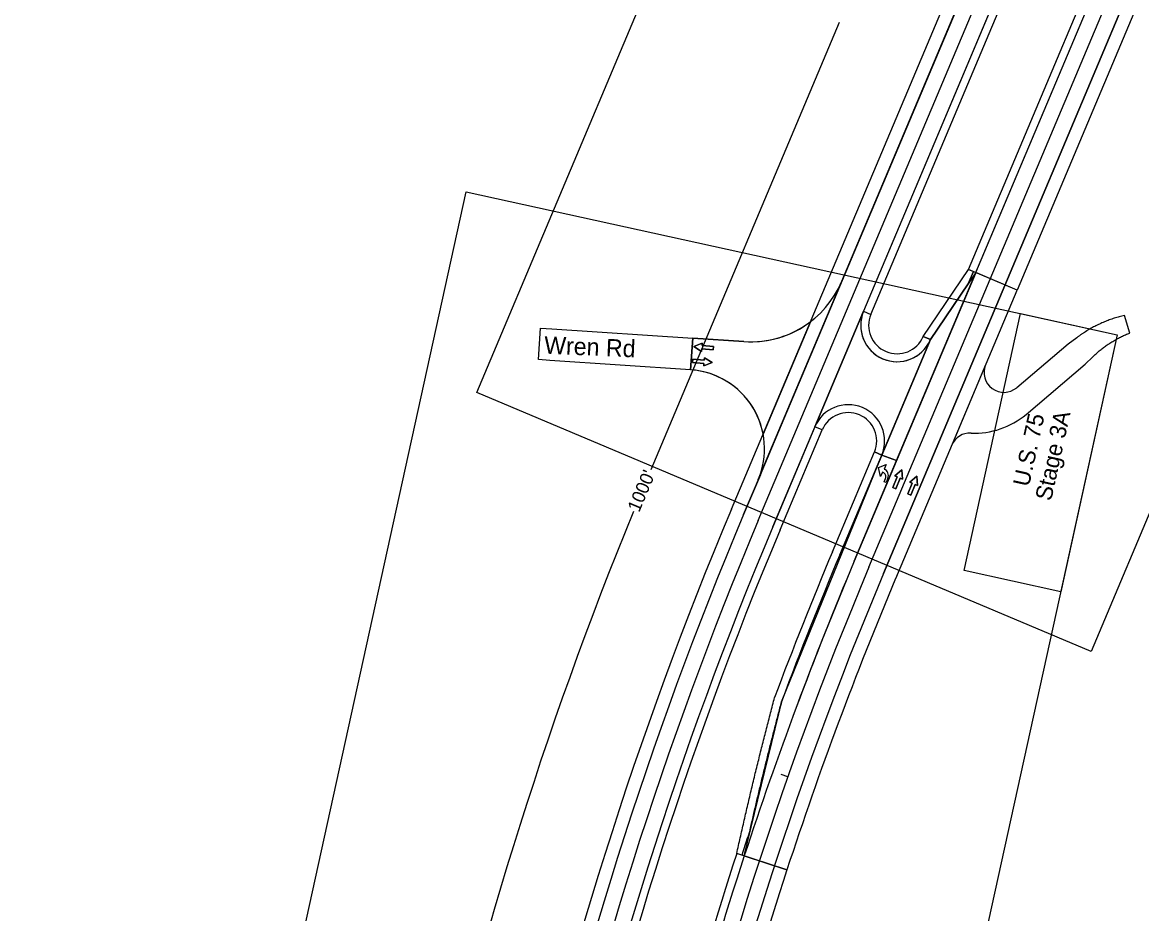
# Model space of a CAD drawing. Extents: x 14104283 to 14120882, y 8635219 to 8671666.
# Drawn here: x 14108596 to 14109444, y 8645129 to 8645804 of the extents above; entities that cross this region are included whole.
import ezdxf

# ---------------------------------------------------------------- set-up
doc = ezdxf.new("R2010")
doc.units = 0
for name, color, linetype in [('Cell', 7, 'Continuous'), ('dsnNonPlotable', 7, 'Continuous'), ('dsnPaintExistingEdgeLineRightWhite', 7, 'Continuous'), ('dsnPaintExistingLaneLineWhite', 7, 'Continuous'), ('dsnPaintPlaceBrokenLineWhite', 7, 'Continuous'), ('dsnPaintPlaceEdgeLineLeftYellow', 7, 'Continuous'), ('dsnPaintPlaceEdgeLineRightWhite', 7, 'Continuous'), ('dsnPaintRemoveDoubleCenterLineYellow', 7, 'Continuous'), ('dsnShadingGranular', 7, 'Continuous'), ('dsnShadingPaved', 7, 'Continuous'), ('dsnStdLabel', 7, 'Continuous'), ('dsnStgShadingPrevPav', 7, 'Continuous'), ('dsnTextFinalPlan', 7, 'Continuous'), ('dsnTextOverlapEven', 7, 'Continuous'), ('TextAlignmentLrg', 7, 'Continuous')]:
    doc.layers.add(name, color=color, linetype=linetype)

msp = doc.modelspace()

# ---------------------------------------------------------------- linework, layer by layer
at = {"layer": 'Cell'}
for p, q in [((14109248.25, 8645463.34), (14109247.95, 8645463.46)), ((14109249.06, 8645465.84), (14109249.23, 8645465.77))]:
    msp.add_line(p, q, dxfattribs=at)
for points in [[(14109119.8, 8645558.61), (14109119.6, 8645556.12), (14109110.88, 8645556.82), (14109110.73, 8645554.95), (14109104.75, 8645558.56), (14109111.23, 8645561.18), (14109111.08, 8645559.31)], [(14109103.82, 8645546.48), (14109104.02, 8645548.97), (14109112.74, 8645548.27), (14109112.89, 8645550.14), (14109118.87, 8645546.53), (14109112.39, 8645543.91), (14109112.54, 8645545.78)], [(14109257.91, 8645450.9), (14109255.59, 8645451.85), (14109258.91, 8645459.95), (14109257.18, 8645460.66), (14109262.44, 8645465.25), (14109262.96, 8645458.29), (14109261.23, 8645459)], [(14109269.36, 8645446.08), (14109267.05, 8645447.03), (14109270.37, 8645455.12), (14109268.63, 8645455.83), (14109273.9, 8645460.43), (14109274.42, 8645453.46), (14109272.68, 8645454.17)]]:
    msp.add_lwpolyline(points, close=True, dxfattribs=at)
for points in [[(14109111.08, 8645559.31), (14109111.23, 8645561.18), (14109104.75, 8645558.56), (14109110.73, 8645554.95), (14109110.88, 8645556.82), (14109119.6, 8645556.12), (14109119.8, 8645558.61), (14109111.08, 8645559.31)], [(14109112.54, 8645545.78), (14109112.39, 8645543.91), (14109118.87, 8645546.53), (14109112.89, 8645550.14), (14109112.74, 8645548.27), (14109104.02, 8645548.97), (14109103.82, 8645546.48), (14109112.54, 8645545.78)], [(14109244.88, 8645466.97), (14109250.61, 8645469.19), (14109249.06, 8645465.84)], [(14109244.88, 8645466.97), (14109250.61, 8645469.19), (14109249.06, 8645465.84)], [(14109247.95, 8645463.46), (14109246.4, 8645460.11), (14109244.88, 8645466.97)], [(14109247.95, 8645463.46), (14109246.4, 8645460.11), (14109244.88, 8645466.97)], [(14109248.25, 8645463.34), (14109247.95, 8645463.46)], [(14109249.06, 8645465.84), (14109249.23, 8645465.77)], [(14109261.23, 8645459), (14109262.96, 8645458.29), (14109262.44, 8645465.25), (14109257.18, 8645460.66), (14109258.91, 8645459.95), (14109255.59, 8645451.85), (14109257.91, 8645450.9), (14109261.23, 8645459)], [(14109272.68, 8645454.17), (14109274.42, 8645453.46), (14109273.9, 8645460.43), (14109268.63, 8645455.83), (14109270.37, 8645455.12), (14109267.05, 8645447.03), (14109269.36, 8645446.08), (14109272.68, 8645454.17)], [(14109251.88, 8645459.03), (14109250.5, 8645455.62), (14109249.11, 8645456.18), (14109250.1, 8645458.62)], [(14109251.88, 8645459.03), (14109250.5, 8645455.62), (14109249.11, 8645456.18), (14109250.1, 8645458.62)]]:
    msp.add_lwpolyline(points, dxfattribs=at)
for centre, major_axis in [((14109246.86, 8645459.93), (-1.38, -3.41)), ((14109246.86, 8645459.93), (-1.38, -3.41)), ((14109247.26, 8645460.9), (-1.97, -4.87)), ((14109247.26, 8645460.9), (-1.97, -4.87))]:
    msp.add_ellipse(centre, major_axis=major_axis, ratio=0.9474, start_param=1.570796, end_param=3.141593, dxfattribs=at)
at = {"layer": 'dsnNonPlotable'}
for points in [[(14108940.51, 8645523.76), (14109549.08, 8646968.3), (14110014.46, 8646772.24), (14109405.89, 8645327.7)], [(14108596.11, 8644144.86), (14108932.49, 8645675.84), (14109425.73, 8645567.47), (14109089.34, 8644036.49)]]:
    msp.add_lwpolyline(points, close=True, dxfattribs=at)
at = {"layer": 'dsnPaintExistingEdgeLineRightWhite'}
msp.add_line((14109248.59, 8645386.79), (14110924.38, 8649364.51), dxfattribs=at)
msp.add_arc((14111877.79, 8644279.13), 2853, 157.1547, 167.84877, dxfattribs=at)
at = {"layer": 'dsnPaintExistingLaneLineWhite'}
msp.add_line((14109226.48, 8645396.11), (14109258.54, 8645472.23), dxfattribs=at)
msp.add_arc((14111877.79, 8644279.13), 2877, 157.1547, 159.50271, dxfattribs=at)
at = {"layer": 'dsnPaintPlaceBrokenLineWhite'}
for p, q in [((14109153.67, 8645426.78), (14110829.45, 8649404.5)), ((14109237.53, 8645391.45), (14110075.43, 8647380.31))]:
    msp.add_line(p, q, dxfattribs=at)
for centre, radius in [((14111877.8, 8644279.13), 2956), ((14111877.79, 8644279.13), 2865)]:
    msp.add_arc(centre, radius, 157.1547, 167.84877, dxfattribs=at)
at = {"layer": 'dsnPaintPlaceEdgeLineLeftYellow'}
for p, q in [((14109318.52, 8645614.6), (14110902.26, 8649373.83)), ((14109283.61, 8645562.93), (14109318.29, 8645614.05)), ((14109196.6, 8645497.77), (14109164.73, 8645422.12)), ((14109171.7, 8645290.75), (14109247.29, 8645476.42)), ((14109143.12, 8645172.82), (14109171.7, 8645290.75))]:
    msp.add_line(p, q, dxfattribs=at)
msp.add_lwpolyline([(14111383.58, 8650689.44), (14110840.51, 8649399.84), (14109233.49, 8645585.32)], dxfattribs=at)
for centre, radius, start, end in [((14109258.83, 8645574.64), 27.5, 157.1547, 335.84151), ((14109221.94, 8645487.09), 27.5, 67.1547, 157.1547), ((14109221.94, 8645487.09), 27.5, 337.1547, 67.1547), ((14111877.8, 8644279.13), 2944, 157.1547, 167.84877), ((14111877.79, 8644279.13), 2877, 161.90302, 167.84877)]:
    msp.add_arc(centre, radius, start, end, dxfattribs=at)
at = {"layer": 'dsnPaintPlaceEdgeLineRightWhite'}
msp.add_line((14109155.29, 8645461.54), (14109142.61, 8645431.44), dxfattribs=at)
msp.add_lwpolyline([(14111344.56, 8650658.61), (14110818.39, 8649409.15), (14109217.02, 8645608.05)], dxfattribs=at)
msp.add_arc((14111877.8, 8644279.13), 2968, 157.1547, 167.84877, dxfattribs=at)
at = {"layer": 'dsnPaintRemoveDoubleCenterLineYellow'}
msp.add_line((14109237.53, 8645391.45), (14110075.43, 8647380.31), dxfattribs=at)
msp.add_arc((14111877.79, 8644279.13), 2865, 157.1547, 167.84877, dxfattribs=at)
at = {"layer": 'dsnShadingGranular'}
msp.add_line((14109325.98, 8645544.73), (14109300.38, 8645483.96), dxfattribs=at)
at = {"layer": 'dsnShadingPaved'}
for p, q in [((14109258.54, 8645472.23), (14110902.26, 8649373.83)), ((14110924.38, 8649364.51), (14109248.59, 8645386.79)), ((14109318.29, 8645614.05), (14109258.54, 8645472.23)), ((14109283.61, 8645562.93), (14109318.29, 8645614.05)), ((14109153.74, 8645457.84), (14109217.02, 8645608.05)), ((14109196.6, 8645497.77), (14109233.49, 8645585.32)), ((14109104.08, 8645564.95), (14109102.47, 8645541)), ((14109142.87, 8645562.34), (14109104.08, 8645564.95)), ((14109171.7, 8645290.75), (14109247.29, 8645476.42)), ((14109247.29, 8645476.42), (14109258.54, 8645472.23)), ((14109258.54, 8645472.23), (14109247.29, 8645476.42)), ((14109143.12, 8645172.82), (14109171.7, 8645290.75))]:
    msp.add_line(p, q, dxfattribs=at)
for points in [[(14118413.25, 8667444.25), (14110818.39, 8649409.15), (14109142.61, 8645431.44)], [(14109164.73, 8645422.12), (14110840.51, 8649399.84), (14118435.37, 8667434.94)]]:
    msp.add_lwpolyline(points, dxfattribs=at)
for centre, radius, start, end in [((14109147.9, 8645637.17), 75, 266.1547, 337.1547), ((14109258.83, 8645574.64), 27.5, 157.1547, 247.1547), ((14109258.83, 8645574.64), 27.5, 247.1547, 335.84151), ((14109098.44, 8645481.13), 60, 337.1547, 86.1547), ((14109221.94, 8645487.09), 27.5, 67.1547, 157.1547), ((14109221.94, 8645487.09), 27.5, 337.1547, 67.1547), ((14111877.8, 8644279.13), 2968, 157.1547, 167.84877), ((14111877.8, 8644279.13), 2944, 157.1547, 167.84877), ((14111877.79, 8644279.13), 2853, 157.1547, 167.84877), ((14111877.79, 8644279.13), 2877, 161.90302, 167.84877)]:
    msp.add_arc(centre, radius, start, end, dxfattribs=at)
at = {"layer": 'dsnStdLabel'}
msp.add_line((14109214.96, 8645804.07), (14109072.17, 8645465.12), dxfattribs=at)
msp.add_arc((14111877.8, 8644279.13), 3046, 157.72718, 167.84877, dxfattribs=at)
at = {"layer": 'dsnStgShadingPrevPav'}
for p, q in [((14109133.4, 8645435.32), (14110809.18, 8649413.03)), ((14110818.39, 8649409.15), (14109142.61, 8645431.44)), ((14109318.52, 8645614.6), (14109226.48, 8645396.11)), ((14109318.52, 8645614.6), (14109226.48, 8645396.11)), ((14109312.8, 8645606.16), (14109316.68, 8645615.38)), ((14109316.68, 8645615.38), (14109318.52, 8645614.6)), ((14109349.86, 8645601.4), (14109318.52, 8645614.6)), ((14109155.29, 8645461.54), (14109217.02, 8645608.05)), ((14109284.17, 8645563.96), (14109312.8, 8645606.16)), ((14109257.81, 8645382.91), (14109349.86, 8645601.4)), ((14109196.6, 8645497.77), (14109233.49, 8645585.32)), ((14109233.49, 8645585.32), (14109196.6, 8645497.77)), ((14109233.49, 8645585.32), (14109239.01, 8645582.99)), ((14109435.19, 8645568.84), (14109431.12, 8645582.24)), ((14109193.28, 8645577.45), (14109157.4, 8645492.29)), ((14109102.47, 8645541), (14109104.08, 8645564.95)), ((14109104.08, 8645564.95), (14109142.87, 8645562.34)), ((14109215.42, 8645400.77), (14109284.17, 8645563.96)), ((14109284.17, 8645563.96), (14109247.29, 8645476.42)), ((14109278.64, 8645566.29), (14109284.17, 8645563.96)), ((14109325.98, 8645544.73), (14109300.38, 8645483.96)), ((14109356.61, 8645507.27), (14109401.37, 8645545.2)), ((14109401.37, 8645545.2), (14109407.22, 8645550.87)), ((14109196.6, 8645497.77), (14109164.73, 8645422.12)), ((14109196.6, 8645497.77), (14109164.73, 8645422.12)), ((14109170.26, 8645419.79), (14109202.13, 8645495.44)), ((14109202.13, 8645495.44), (14109196.6, 8645497.77)), ((14109202.13, 8645495.44), (14109196.6, 8645497.77)), ((14109209.89, 8645403.09), (14109241.76, 8645478.75)), ((14109247.29, 8645476.42), (14109215.42, 8645400.77)), ((14109247.29, 8645476.42), (14109241.76, 8645478.75)), ((14109241.76, 8645478.75), (14109247.29, 8645476.42)), ((14109142.61, 8645431.44), (14109155.29, 8645461.54)), ((14109175.44, 8645162.26), (14109137.42, 8645174.69)), ((14109141.22, 8645173.44), (14109137.42, 8645174.69)), ((14109143.12, 8645172.82), (14109141.22, 8645173.44)), ((14109143.12, 8645172.82), (14109175.44, 8645162.26))]:
    msp.add_line(p, q, dxfattribs=at)
for points in [[(14109239.01, 8645582.99), (14111389.11, 8650687.11), (14111383.58, 8650689.44), (14109233.49, 8645585.32)], [(14109313, 8645616.93), (14110622.7, 8648725.72), (14110659.7, 8648710.5), (14109349.86, 8645601.4)], [(14109278.64, 8645566.29), (14109313, 8645616.93), (14109316.68, 8645615.38), (14109312.8, 8645606.16), (14109284.17, 8645563.96)], [(14108987.25, 8645548.72), (14108988.7, 8645572.67), (14108997.4, 8645572.12), (14109104.08, 8645564.95), (14109102.47, 8645541), (14108995.79, 8645548.17)]]:
    msp.add_lwpolyline(points, close=True, dxfattribs=at)
for points in [[(14111383.58, 8650689.44), (14110840.51, 8649399.84), (14109233.49, 8645585.32)], [(14109217.02, 8645608.05), (14110818.39, 8649409.15), (14111344.56, 8650658.61)], [(14109395, 8645565.3), (14109388.44, 8645560.45), (14109349.5, 8645527.46)]]:
    msp.add_lwpolyline(points, dxfattribs=at)
for centre, radius, start, end in [((14109258.83, 8645574.64), 21.5, 157.1547, 247.1547), ((14109147.9, 8645637.17), 75, 266.1547, 307.22827), ((14109258.83, 8645574.64), 21.5, 247.1547, 337.1547), ((14109339.81, 8645538.91), 15, 157.1547, 310.2778), ((14109098.44, 8645481.13), 60, 10.71201, 86.1547), ((14109221.94, 8645487.09), 21.5, 67.1547, 157.1547), ((14109221.94, 8645487.09), 21.5, 337.1547, 67.1547), ((14109317.82, 8645553.05), 60, 267.23357, 310.2778), ((14109314.2, 8645478.13), 15, 87.23357, 157.1547), ((14111877.8, 8644279.13), 2978, 157.1547, 167.84877), ((14111877.8, 8644279.13), 2968, 157.1547, 167.84877), ((14111877.8, 8644279.13), 2968, 157.1547, 167.84877), ((14111877.8, 8644279.13), 2944, 157.1547, 167.84877), ((14111877.8, 8644279.13), 2944, 157.1547, 167.84877), ((14111877.8, 8644279.13), 2938, 157.1547, 167.84877), ((14111877.79, 8644279.13), 2895, 157.1547, 159.50271), ((14111877.79, 8644279.13), 2889, 157.1547, 159.50271), ((14111877.79, 8644279.13), 2889, 157.1547, 159.50271), ((14111877.79, 8644279.13), 2877, 157.1547, 161.90253), ((14111877.79, 8644279.13), 2877, 157.1547, 161.90253), ((14111877.79, 8644279.13), 2843, 157.1547, 161.90253), ((14111877.79, 8644279.13), 2879, 161.50256, 161.90253), ((14111877.79, 8644279.13), 2879, 161.50256, 161.90253), ((14111877.79, 8644279.13), 2883, 161.90253, 167.84877), ((14111877.79, 8644279.13), 2843, 161.90253, 167.84877)]:
    msp.add_arc(centre, radius, start, end, dxfattribs=at)
for points in [[(14109431.12, 8645582.24), (14109430.48, 8645582.08), (14109429.19, 8645581.77), (14109427.27, 8645581.25), (14109425.36, 8645580.69), (14109423.46, 8645580.1), (14109421.57, 8645579.46), (14109419.69, 8645578.78), (14109417.82, 8645578.07), (14109415.97, 8645577.31), (14109414.12, 8645576.52), (14109412.3, 8645575.69), (14109410.49, 8645574.81), (14109408.69, 8645573.91), (14109406.91, 8645572.96), (14109405.15, 8645571.98), (14109403.4, 8645570.95), (14109401.68, 8645569.9), (14109399.98, 8645568.8), (14109398.29, 8645567.67), (14109396.63, 8645566.51), (14109395.54, 8645565.7), (14109395, 8645565.3)], [(14109407.22, 8645550.87), (14109407.62, 8645551.25), (14109408.41, 8645552.02), (14109409.62, 8645553.14), (14109410.86, 8645554.24), (14109412.12, 8645555.32), (14109413.4, 8645556.37), (14109414.71, 8645557.39), (14109416.05, 8645558.39), (14109417.4, 8645559.37), (14109418.77, 8645560.31), (14109420.17, 8645561.23), (14109421.59, 8645562.13), (14109423.03, 8645562.99), (14109424.48, 8645563.83), (14109425.96, 8645564.64), (14109427.45, 8645565.41), (14109428.97, 8645566.16), (14109430.5, 8645566.88), (14109432.04, 8645567.57), (14109433.61, 8645568.23), (14109434.66, 8645568.64), (14109435.19, 8645568.84)], [(14109137.42, 8645174.69), (14109137.85, 8645176.66), (14109138.73, 8645180.61), (14109140.05, 8645186.54), (14109141.39, 8645192.46), (14109142.74, 8645198.38), (14109144.1, 8645204.29), (14109145.48, 8645210.21), (14109146.86, 8645216.13), (14109148.27, 8645222.04), (14109149.68, 8645227.95), (14109151.11, 8645233.86), (14109152.55, 8645239.77), (14109154, 8645245.67), (14109155.46, 8645251.58), (14109156.94, 8645257.48), (14109158.43, 8645263.38), (14109159.94, 8645269.28), (14109161.45, 8645275.17), (14109162.98, 8645281.07), (14109164.52, 8645286.96), (14109165.56, 8645290.89), (14109166.08, 8645292.85)], [(14109147.53, 8645192.53), (14109147.9, 8645194.17), (14109148.65, 8645197.45), (14109149.78, 8645202.37), (14109150.93, 8645207.29), (14109152.08, 8645212.21), (14109153.24, 8645217.13), (14109154.41, 8645222.05), (14109155.58, 8645226.96), (14109156.77, 8645231.88), (14109157.97, 8645236.79), (14109159.17, 8645241.7), (14109160.38, 8645246.61), (14109161.6, 8645251.52), (14109162.83, 8645256.43), (14109164.07, 8645261.34), (14109165.32, 8645266.24), (14109166.58, 8645271.15), (14109167.85, 8645276.05), (14109169.12, 8645280.95), (14109170.4, 8645285.85), (14109171.27, 8645289.12), (14109171.7, 8645290.75)], [(14109171.7, 8645290.75), (14109171.27, 8645289.12), (14109170.4, 8645285.85), (14109169.12, 8645280.95), (14109167.85, 8645276.05), (14109166.58, 8645271.15), (14109165.32, 8645266.24), (14109164.07, 8645261.34), (14109162.83, 8645256.43), (14109161.6, 8645251.52), (14109160.38, 8645246.61), (14109159.17, 8645241.7), (14109157.97, 8645236.79), (14109156.77, 8645231.88), (14109155.58, 8645226.96), (14109154.41, 8645222.05), (14109153.24, 8645217.13), (14109152.08, 8645212.21), (14109150.93, 8645207.29), (14109149.78, 8645202.37), (14109148.65, 8645197.45), (14109147.9, 8645194.17), (14109147.53, 8645192.53)]]:
    msp.add_open_spline(points, degree=3, dxfattribs=at)
at = {"layer": 'dsnTextOverlapEven'}
for points in [[(14109425.73, 8645567.47), (14109382.96, 8645372.83), (14109309.71, 8645388.93), (14109352.48, 8645583.57)], [(14109309.71, 8645388.93), (14109352.48, 8645583.57), (14109425.73, 8645567.47), (14109382.96, 8645372.83)]]:
    msp.add_lwpolyline(points, close=True, dxfattribs=at)
at = {"layer": 'TextAlignmentLrg'}
msp.add_line((14109176.12, 8645232.64), (14109170.97, 8645234.45), dxfattribs=at)

# ---------------------------------------------------------------- texts
at = {"layer": 'dsnStdLabel'}
msp.add_text("1000'", height=10, rotation=67.05307, dxfattribs=at).set_placement((14109063.42, 8645432.55))
at = {"layer": 'dsnTextFinalPlan'}
msp.add_text('Wren Rd', height=13.125, rotation=357.6374, dxfattribs=at).set_placement((14108991.27, 8645553.28))
at = {"layer": 'dsnTextOverlapEven'}
for s, p in [('U.S. 75', (14109358.74, 8645451.91)), ('Stage 3A', (14109375.58, 8645441.15))]:
    msp.add_text(s, height=12.5, rotation=77.60784, dxfattribs=at).set_placement(p)

doc.saveas('drawing.dxf')
